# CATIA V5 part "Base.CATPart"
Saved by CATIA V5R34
Part number: Part1
Bounding box of the stored display mesh (mm): x -123.1 to 123.1, y -33 to 28, z -30 to 0
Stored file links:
  C:\Users\Apolinar\Desktop\cnc\Base.CATPart
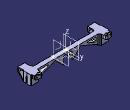
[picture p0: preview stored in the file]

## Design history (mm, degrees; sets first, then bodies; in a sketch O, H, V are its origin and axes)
AxisSystem1: origin (0, 0, 0), X (1, 0, 0), Y (0, 1, 0), Z (0, 0, 1)
Body1 (main body)
  DatumCurve1 to DatumCurve6
  Sketch1 on XY plane of AxisSystem1, origin (0, 0, 0), H (1, 0, 0), V (0, 1, 0)
    line L1 (-97, 9.9983) -> (-97, 10.8787)
    line L2 (-99.1213, 13) -> (-120.9787, 13)
    line L3 (-123.1, 10.8787) -> (-123.1, 0)
    point P1 (-110, 0)
    arc A1 centre (-94, 9.9983) radius 3 from (-93.9, 7) to (-97, 9.9983) cw
    point P2 (-93.9, 7)
    point P3 (-97, 9.9983)
    line L4 (-120.9787, 13) -> (-123.1, 10.8787)
    point P5 (-120.9787, 13)
    point P6 (-123.1, 10.8787)
    line L5 (-97, 10.8787) -> (-99.1213, 13)
    point P7 (-97, 10.8787)
    point P8 (-99.1213, 13)
    line L6 (-93.9, 7) -> (-93.9, 0)
    axis line L7 (-70.1752, 0) -> (-129.1057, 0)
    point P9 (-70.1752, 0)
    point P10 (-129.1057, 0)
    point P11 (-93.9, 0)
    point P12 (-123.1, 0)
    reference projected line E1 (-120, 3.75) -> (-120, 8.5) from edge of DatumCurve1
    point P13 (-93.9, -7)
    point P14 (-97, -9.9983)
    point P16 (-120.9787, -13)
    point P17 (-123.1, -10.8787)
    point P18 (-97, -10.8787)
    point P19 (-99.1213, -13)
    line L8 (-97, -9.9983) -> (-97, -10.8787)
    line L9 (-99.1213, -13) -> (-120.9787, -13)
    arc A2 centre (-94, -9.9983) radius 3 from (-93.9, -7) to (-97, -9.9983) ccw
    line L10 (-120.9787, -13) -> (-123.1, -10.8787)
    line L11 (-97, -10.8787) -> (-99.1213, -13)
    point P20 (-93.9, 0)
    line L12 (-93.9, -7) -> (-93.9, 0)
    point P21 (-123.1, 0)
    line L13 (-123.1, -10.8787) -> (-123.1, 0)
    point P22 (-110.05, 0)
    line L14 (-100, 10) -> (-100, -10)
    line L15 (-100, -10) -> (-120.1, -10)
    line L16 (-120.1, -10) -> (-120.1, 10)
    line L17 (-120.1, 10) -> (-100, 10)
    point P23 (-100, 10)
    point P24 (-100, -10)
    point P25 (-120.1, -10)
    point P26 (-120.1, 10)
    reference projected line E2 (-120, -8.5) -> (-120, -3.75) from edge of DatumCurve4
    point P27 (110, 0)
    point P28 (93.9, 7)
    point P29 (97, 9.9983)
    point P31 (120.9787, 13)
    point P32 (123.1, 10.8787)
    point P33 (97, 10.8787)
    point P34 (99.1213, 13)
    point P35 (129.1057, 0)
    point P36 (93.9, 0)
    point P37 (123.1, 0)
    point P38 (93.9, -7)
    point P39 (97, -9.9983)
    point P41 (120.9787, -13)
    point P42 (123.1, -10.8787)
    point P43 (97, -10.8787)
    point P44 (99.1213, -13)
    point P45 (93.9, 0)
    point P46 (123.1, 0)
    point P47 (110.05, 0)
    point P48 (100, 10)
    point P49 (100, -10)
    point P50 (120.1, -10)
    point P51 (120.1, 10)
    line L18 (97, 9.9983) -> (97, 10.8787)
    line L19 (99.1213, 13) -> (120.9787, 13)
    line L20 (123.1, 10.8787) -> (123.1, 0)
    arc A3 centre (94, 9.9983) radius 3 from (93.9, 7) to (97, 9.9983) ccw
    line L21 (120.9787, 13) -> (123.1, 10.8787)
    line L22 (97, 10.8787) -> (99.1213, 13)
    line L23 (93.9, 7) -> (93.9, 0)
    line L24 (97, -9.9983) -> (97, -10.8787)
    line L25 (99.1213, -13) -> (120.9787, -13)
    arc A4 centre (94, -9.9983) radius 3 from (93.9, -7) to (97, -9.9983) cw
    line L26 (120.9787, -13) -> (123.1, -10.8787)
    line L27 (97, -10.8787) -> (99.1213, -13)
    line L28 (93.9, -7) -> (93.9, 0)
    line L29 (123.1, -10.8787) -> (123.1, 0)
    line L30 (100, 10) -> (100, -10)
    line L31 (100, -10) -> (120.1, -10)
    line L32 (120.1, -10) -> (120.1, 10)
    line L33 (120.1, 10) -> (100, 10)
    reference projected line E3 (-113.75, 10) -> (-118.5, 10) from edge of DatumCurve5
    reference projected line E4 (-100, -8.5) -> (-100, -3.75) from edge of DatumCurve6
    radius A1 = 3
    angle L2 L4 = 45
    length L4 = 3
    angle L1 L5 = 45
    length L5 = 3
    distance L6 V = 93.9
    distance P2 H = 7
    distance E1 L3 = 3.1
    distance L16 E2 = 0.1
    distance L2 L17 = 3
    distance L14 P7 = 3
    vertical: L1 V, L3 V, L6 V, L14 V, L16 V
    horizontal: L2 H, L7 H, L15 H, L17 H
    coincidence: P1 H, P9 H, L7 P11, L7 P12, P22 L7, P11 P20, P12 P21, P36 P45, P37 P46, L17 E3, L14 E4
    tangency: A1 L1
    symmetry: P2 P13 H, P3 P14 H, P5 P16 H, P6 P17 H, P7 P18 H, P8 P19 H, L1 L8 H, L2 L9 H, A1 A2 H, L4 L10 H, L5 L11 H, P11 P20 H, L6 L12 H, P12 P21 H, L3 L13 H, P1 P27 V, P2 P28 V, P3 P29 V, P5 P31 V, P6 P32 V, P7 P33 V, P8 P34 V, P10 P35 V, P11 P36 V, P12 P37 V, P13 P38 V, P14 P39 V, P16 P41 V, P17 P42 V, P18 P43 V, P19 P44 V, P20 P45 V, P21 P46 V, P22 P47 V, P23 P48 V, P24 P49 V, P25 P50 V, P26 P51 V, L1 L18 V, L2 L19 V, L3 L20 V, A1 A3 V, L4 L21 V, L5 L22 V, L6 L23 V, L8 L24 V, L9 L25 V, A2 A4 V, L10 L26 V, L11 L27 V, L12 L28 V, L13 L29 V, L14 L30 V, L15 L31 V, L16 L32 V, L17 L33 V
    equidistance: L14 L16 P22, L15 L17 P22
  Pad1: profile Sketch1, direction (0, 0, -1), length 30
  Sketch2 on XY plane of AxisSystem1, origin (0, 0, 0), H (1, 0, 0), V (0, 1, 0)
    line L1 (93.9, 7) -> (93.9, -7)
    line L2 (93.9, -7) -> (-93.9, -7)
    line L3 (-93.9, -7) -> (-93.9, 7)
    line L4 (-93.9, 7) -> (93.9, 7)
    reference projected line E1 (-93.9, -7) -> (-93.9, 0) from edge [face of Pad1 from Sketch1.L12 | start face of Pad1]
    distance L2 L4 = 14
    vertical: L1 V, L3 V
    horizontal: L2 H, L4 H
    equidistance: L1 L3 O, L2 L4 O
    coincidence: L3 E1
  Pad2: profile Sketch2, direction (0, 0, -1), length 5
  Sketch3 on end face of Pad2, origin (0, 0, -5), H (1, 0, 0), V (0, -1, 0)
    line L1 (15, 7) -> (15, -7)
    line L2 (15, -7) -> (-15, -7)
    line L3 (-15, -7) -> (-15, 7)
    line L4 (-15, 7) -> (15, 7)
    reference projected line E1 (-93.9, 7) -> (93.9, 7) from edge [end face of Pad2 | face of Pad2 from Sketch2.L2]
    length L4 = 30
    vertical: L1 V, L3 V
    horizontal: L2 H, L4 H
    equidistance: L1 L3 O, L2 L4 O
    coincidence: L4 E1
  Pad3: profile Sketch3, direction (0, 0, -1), length 25
  Sketch4 on face of Pad3, origin (0, -7, 0), H (1, 0, 0), V (0, 0, 1)
    point P1 (0, -17.5)
    line L1 (13, -5) -> (13, -30)
    line L2 (13, -30) -> (-13, -30)
    line L3 (-13, -30) -> (-13, -5)
    line L4 (-13, -5) -> (13, -5)
    reference projected line E1 (-15, -5) -> (-15, -30) from edge [face of Pad3 from Sketch3.L3 | face of Pad3]
    reference projected line E2 (15, -30) -> (-15, -30) from edge [face of Pad3 from Sketch3.L4 | end face of Pad3]
    reference projected line E3 (-93.9, -5) -> (93.9, -5) from edge [end face of Pad2 | face of Pad3]
    distance E1 L3 = 2
    coincidence: P1 V, E2 L2, L4 E3
    vertical: L1 V, L3 V
    horizontal: L2 H, L4 H
    equidistance: L1 L3 P1, L2 L4 P1
  Pocket1: profile Sketch4, direction (0, 1, 0), through (limit type 6)
  Chamfer1: length 25, angle 45, on edge [end face of Pad2 | face of Pad3 from Sketch3.L1]; edge [end face of Pad2 | face of Pad3 from Sketch3.L3]
  Sketch5 on YZ plane of AxisSystem1, origin (0, 0, 0), H (0, 1, 0), V (0, 0, 1)
    circle A1 centre (0, -20) radius 2.5
    point P1 (0, -20)
    point P2 (0, -21.0856)
    reference projected line E1 (-7, -30) -> (7, -30) from edge [end face of Pad3 | face of Pocket1 from Sketch4.L3]
    distance E1 P1 = 10
    radius A1 = 2.5
    coincidence: V P1
  Pocket2: profile Sketch5, direction (-1, 0, 0), through (limit type 6), opposite side through (limit type 6)
  Plane1: type Offset, RefPlane YZ plane of AxisSystem1, Offset 16
  Plane2: type Offset, RefPlane YZ plane of AxisSystem1, Offset 16, reversed
  Sketch6 on Plane2, origin (-16, 0, 0), H (0, 1, 0), V (0, 0, 1)
    circle A1 centre (0, -20) radius 5
    point P1 (0, -20)
    reference projected circle E1 centre (0, -20) radius 2.5 from edge [face of Pocket2 from Sketch5.A1 | face of Chamfer1]
    radius A1 = 5
    coincidence: P1 V
    concentricity: P1 E1
  Pocket3: profile Sketch6, direction (-1, 0, 0), length 15
  Fillet1: radius 2, on edge [end face of Pad3 | face of Pocket1 from Sketch4.L3]; edge [face of Pocket1 from Sketch4.L1 | end face of Pad3]; edge [face of Pocket1 from Sketch4.L3 | face of Pocket1 from Sketch4.L4]; edge [face of Pocket1 from Sketch4.L4 | face of Pocket1 from Sketch4.L1]
  Sketch7 on face of Pad1 from Sketch1.L3, origin (-123.1, 0, 0), H (0, -1, 0), V (0, 0, 1)
    construction line L1 (0, -12.5) -> (0, -30)
    point P1 (0, -12.5)
    point P2 (0, -30)
    line L2 (2.5, -12.5) -> (2.5, -30)
    line L3 (-2.5, -30) -> (-2.5, -12.5)
    arc A1 centre (0, -30) radius 2.5 from (2.5, -30) to (-2.5, -30) cw
    arc A2 centre (0, -12.5) radius 2.5 from (-2.5, -12.5) to (2.5, -12.5) cw
    reference projected line E1 (0, -30) -> (10.8787, -30) from edge [end face of Pad1 | face of Pad1 from Sketch1.L13]
    distance L1 L2 = 2.5
    distance A2 H = 10
    coincidence: P1 V, P2 E1
    vertical: L1 V
    tangency: A1 L2, A2 L2, A1 L3, A2 L3
  Pocket4: profile Sketch7, direction (1, 0, 0), length 10
  Mirror1: of Pocket4, about YZ plane of AxisSystem1
  Sketch8 on XY plane of AxisSystem1, origin (0, 0, 0), H (1, 0, 0), V (0, 1, 0)
    point P1 (-120, 13)
    line L1 (-120, 13) -> (-100, 13)
    line L2 (-100, 13) -> (-100, 28)
    line L3 (-100, 28) -> (-120, 28)
    line L4 (-120, 28) -> (-120, 22)
    point P2 (-100, 13)
    point P3 (-100, 28)
    point P4 (-120, 28)
    reference projected line E1 (-99.0213, 13) -> (-120.9787, 13) from edge [face of Pad1 from Sketch1.L2 | start face of Pad1]
    arc A1 centre (-107, 21) radius 4 from (-110.873, 20) to (-110.873, 22) ccw
    point P5 (-107, 21)
    reference projected line E2 (-100, -10.1) -> (-100, 10.1) from edge [start face of Pad1 | face of Pad1 from Sketch1.L14]
    point P6 (-113.9259, 18.1)
    line L5 (-110.873, 20) -> (-120, 20)
    line L6 (-120, 22) -> (-110.873, 22)
    point P7 (-110.873, 22)
    point P8 (-110.873, 20)
    point P9 (-120, 20)
    point P10 (-120, 22)
    line L7 (-120, 20) -> (-120, 13)
    point P11 (120, 13)
    point P12 (100, 13)
    point P13 (100, 28)
    point P14 (120, 28)
    point P16 (113.9259, 18.1)
    point P17 (110.873, 22)
    point P18 (110.873, 20)
    point P19 (120, 20)
    point P20 (120, 22)
    line L8 (120, 13) -> (100, 13)
    line L9 (100, 13) -> (100, 28)
    line L10 (100, 28) -> (120, 28)
    line L11 (120, 28) -> (120, 22)
    arc A2 centre (107, 21) radius 4 from (110.873, 20) to (110.873, 22) cw
    line L12 (110.873, 20) -> (120, 20)
    line L13 (120, 22) -> (110.873, 22)
    line L14 (120, 20) -> (120, 13)
    length L3 = 20
    length L2 = 15
    radius A1 = 4
    distance A1 L3 = 3
    distance A1 L2 = 3
    distance L5 P5 = 1
    distance P10 P5 V = 1
    horizontal: L1 H, L3 H, L5 H, L6 H
    vertical: L2 V, L4 V, L7 V
    coincidence: L1 E1, E2 L2, L4 L7
    symmetry: P1 P11 V, P2 P12 V, P3 P13 V, P4 P14 V, P6 P16 V, P7 P17 V, P8 P18 V, P9 P19 V, P10 P20 V, L1 L8 V, L2 L9 V, L3 L10 V, L4 L11 V, A1 A2 V, L5 L12 V, L6 L13 V, L7 L14 V
  Pad4: profile Sketch8, direction (0, 0, -1), length 10
  Chamfer2: length 4, angle 75, on edge [face of Pad4 from Sketch8.L3 | face of Pad4 from Sketch8.L4]
  Chamfer3: length 4, angle 45, on edge [face of Pad4 from Sketch8.L2 | face of Pad4 from Sketch8.L3]
  Chamfer4: length 0.8, angle 80, on edge [face of Pad1 from Sketch1.L2 | face of Pad4 from Sketch8.L2]
  Chamfer5: length 4, angle 75, on edge [face of Pad4 from Sketch8.L11 | face of Pad4 from Sketch8.L10]
  Chamfer6: length 4, angle 45, on edge [face of Pad4 from Sketch8.L10 | face of Pad4 from Sketch8.L9]
  Chamfer7: length 0.8, angle 80, on edge [face of Pad4 from Sketch8.L9 | face of Pad1 from Sketch1.L19]
  Sketch9 on face of Pad4 from Sketch8.L3, origin (0, 28, 0), H (-1, 0, 0), V (0, 0, 1)
    circle A1 centre (116.25, -5) radius 1.75
    point P1 (116.25, -5)
    reference projected line E1 (120, 0) -> (105.0718, 0) from edge [face of Pad4 | face of Chamfer2]
    reference projected line E2 (120, 0) -> (120, -10) from edge [face of Chamfer2 | face of Pad4 from Sketch8.L4]
    distance P1 E1 = 5
    distance A1 E2 = 2
    radius A1 = 1.75
  Pocket5: profile Sketch9, direction (0, -1, 0), length 15
  Sketch10 on face of Pad1 from Sketch1.L2, origin (0, 13, 0), H (-1, 0, 0), V (0, 0, 1)
    point P2 (116.25, -2.3)
    construction circle A1 centre (116.25, -5) radius 3.1177
    construction circle A2 centre (116.25, -5) radius 2.7
    point P3 (117.8088, -2.3)
    point P4 (114.6912, -2.3)
    point P5 (113.1323, -5)
    point P6 (114.6912, -7.7)
    point P7 (117.8088, -7.7)
    line L1 (117.8088, -2.3) -> (114.6912, -2.3)
    line L2 (114.6912, -2.3) -> (113.1323, -5)
    line L3 (113.1323, -5) -> (114.6912, -7.7)
    line L4 (114.6912, -7.7) -> (117.8088, -7.7)
    construction line L5 (116.25, -5) -> (116.25, -2.3)
    reference projected circle E1 centre (116.25, -5) radius 1.75 from edge [face of Chamfer2 | face of Pocket5 from Sketch9.A1]
    line L6 (117.8088, -2.3) -> (120.9787, -2.3)
    line L7 (120.9787, -2.3) -> (120.9787, -7.7)
    line L8 (120.9787, -7.7) -> (117.8088, -7.7)
    reference projected line E2 (120.9787, 0) -> (120.9787, -30) from edge [face of Pad1 from Sketch1.L2 | face of Pad1 from Sketch1.L4]
    distance L1 L4 = 5.4
    coincidence: A1 P3, A1 P4, A1 P5, A1 P6, A1 P7, E2 L7
    tangency: A2 L1, A2 L2, A2 L3, A2 L4, L6 A2
    midpoint: P2 L1
    vertical: L5 V, L7 V
    concentricity: A2 E1
    horizontal: L8 H
  Pocket6: profile Sketch10, direction (0, 1, 0), length 3
  Mirror2: of Pocket5, Pocket6, about YZ plane of AxisSystem1
  Fillet2: radius 2, on edge [face of Pad4 from Sketch8.L6 | face of Pad4 from Sketch8.A1]; edge [face of Pad4 from Sketch8.A1 | face of Pad4 from Sketch8.L5]
  Fillet3: radius 2, on edge [face of Pad4 from Sketch8.A2 | face of Pad4 from Sketch8.L13]; edge [face of Pad4 from Sketch8.L12 | face of Pad4 from Sketch8.A2]
  Chamfer8: length 22.5, angle 67, on edge [end face of Pad2 | face of Pad1 from Sketch1.L6]; edge [end face of Pad2 | face of Pad1 from Sketch1.L28]
  Sketch11 on face of Pad3, origin (0, 7, 0), H (-1, 0, 0), V (0, 0, 1)
    point P1 (-89, -19.9883)
    line L1 (-89, -19.9883) -> (-89, -5)
    point P2 (-89, -5)
    line L2 (-89, -5) -> (-53.6898, -5)
    point P3 (-53.6898, -5)
    line L3 (-53.6898, -5) -> (-89, -19.9883)
    reference projected line E1 through (-94, 0) direction (0, 1) from axis of face of Pad1 from Sketch1.A3
    reference projected line E2 (-93.7641, -27.4423) -> (-34.5538, -2.309) from edge [face of Chamfer8 | face of Pad3]
    reference projected line E3 (-93.9, 0) -> (93.9, 0) from edge [face of Pad3 | face of Pad4]
    point P4 (89, -19.9883)
    point P5 (89, -5)
    point P6 (53.6898, -5)
    line L4 (89, -19.9883) -> (89, -5)
    line L5 (89, -5) -> (53.6898, -5)
    line L6 (53.6898, -5) -> (89, -19.9883)
    distance L1 E1 = 5
    distance L3 E2 = 5
    distance L2 E3 = 5
    vertical: L1 V
    horizontal: L2 H
    symmetry: P1 P4 V, P2 P5 V, P3 P6 V, L1 L4 V, L2 L5 V, L3 L6 V
  Pocket7: profile Sketch11, direction (0, -1, 0), through (limit type 6)
  Sketch12 on face of Pad4, origin (0, 0, 0), H (1, 0, 0), V (0, 1, 0)
    projected line E1 (100, -10) -> (120.1, -10) from edge [face of Pad4 | face of Pad1 from Sketch1.L31]
    projected line E2 (100, 10) -> (100, -10) from edge [face of Pad4 | face of Pad1 from Sketch1.L30]
    projected line E3 (120.1, 10) -> (100, 10) from edge [face of Pad4 | face of Pad1 from Sketch1.L33]
    projected line E4 (120.1, -10) -> (120.1, 10) from edge [face of Pad4 | face of Pad1 from Sketch1.L32]
    projected line E5 (-120.1, -10) -> (-100, -10) from edge [face of Pad4 | face of Pad1 from Sketch1.L15]
    projected line E6 (-120.1, 10) -> (-120.1, -10) from edge [face of Pad4 | face of Pad1 from Sketch1.L16]
    projected line E7 (-100, 10) -> (-120.1, 10) from edge [face of Pad4 | face of Pad1 from Sketch1.L17]
    projected line E8 (-100, -10) -> (-100, 10) from edge [face of Pad4 | face of Pad1 from Sketch1.L14]
  Pad5: profile Sketch12, direction (0, 0, -1), length 3
  Fillet4: radius 2, on edge [face of Pocket7 from Sketch11.L3 | face of Pocket7 from Sketch11.L1]; edge [face of Pocket7 from Sketch11.L1 | face of Pocket7 from Sketch11.L2]; edge [face of Pocket7 from Sketch11.L2 | face of Pocket7 from Sketch11.L3]; edge [face of Pocket7 from Sketch11.L4 | face of Pocket7 from Sketch11.L6]; edge [face of Pocket7 from Sketch11.L5 | face of Pocket7 from Sketch11.L4]; edge [face of Pocket7 from Sketch11.L6 | face of Pocket7 from Sketch11.L5]
  Sketch13 on face of Pad1 from Sketch1.L25, origin (0, -13, 0), H (1, 0, 0), V (0, 0, 1)
  Pad6: profile Sketch13, direction (0, -1, 0), length 20
  Chamfer9: length 20, angle 45, on edge [face of Pad6 | end face of Pad6] (x2)
  Chamfer10: length 3, angle 45, on edge [face of Pad6 | end face of Pad6] (x6)
  Sketch14 on face of Pad6, origin (120.9787, 0, 0), H (0, 1, 0), V (0, 0, 1)
    line L1 (-27, -3) -> (-13, -3)
    line L2 (-13, -3) -> (-13, -25.7574)
    line L3 (-13, -25.7574) -> (-27, -11.7574)
    line L4 (-27, -11.7574) -> (-27, -3)
    reference projected line E1 (-13, 0) -> (-33, 0) from edge [face of Pad6 | face of Pad6]
    reference projected line E2 (-13, 0) -> (-13, -30) from edge [face of Pad6 | face of Pad1 from Sketch1.L26]
    reference projected line E3 (-13, -30) -> (-33, -10) from edge [face of Pad6 | face of Chamfer9]
    reference intersected line E4 (-30, -13) -> (-30, 0) from face of Chamfer10
    distance L1 E1 = 3
    distance E3 L3 = 3
    distance L4 E4 = 3
    horizontal: L1 H
    vertical: L2 V, L4 V
    coincidence: L2 E2
  Pocket8: profile Sketch14, direction (-1, 0, 0), through (limit type 3)
  Mirror3: of Pocket3, about YZ plane of AxisSystem1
